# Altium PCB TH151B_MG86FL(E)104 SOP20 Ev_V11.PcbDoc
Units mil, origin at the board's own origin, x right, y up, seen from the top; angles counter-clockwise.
Board outline 2850 x 2110 mil, 2 copper layers (Top Layer, Bottom Layer); 47 components, 39 nets, 238 pads, 101 vias.
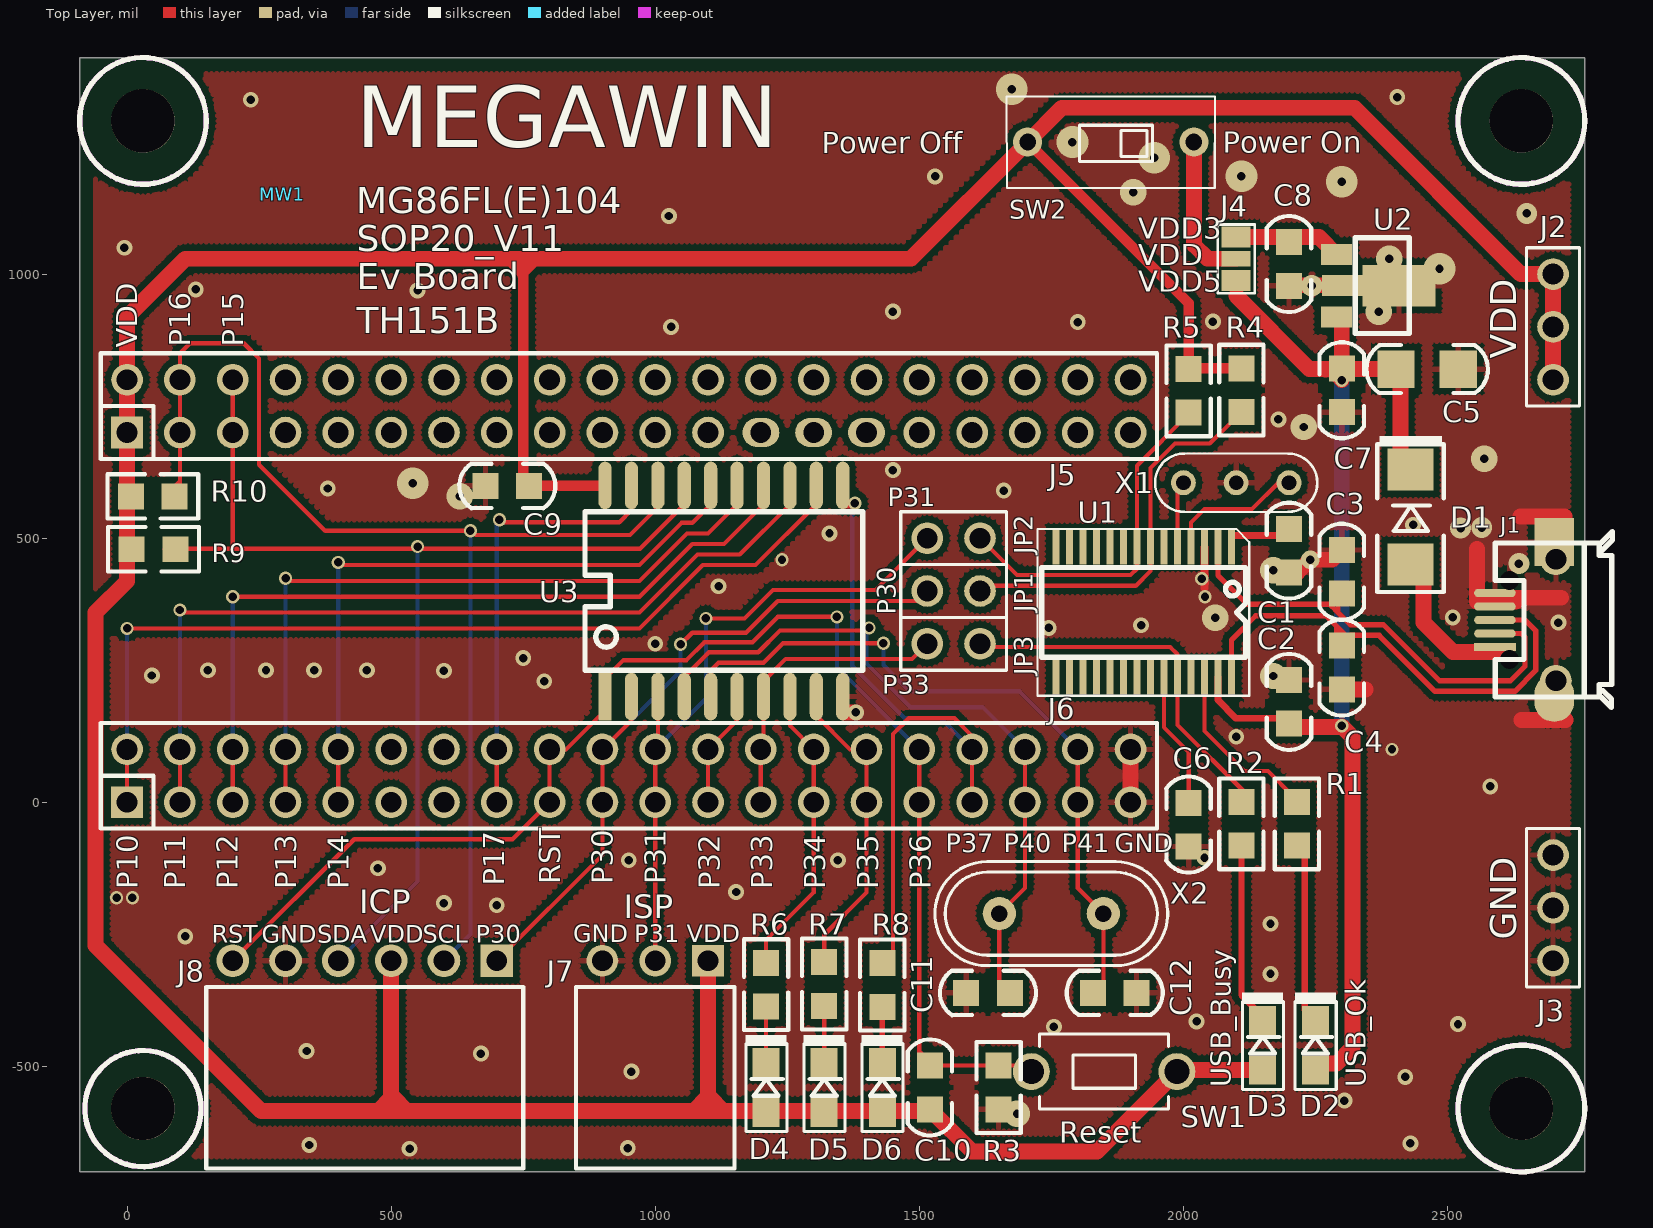
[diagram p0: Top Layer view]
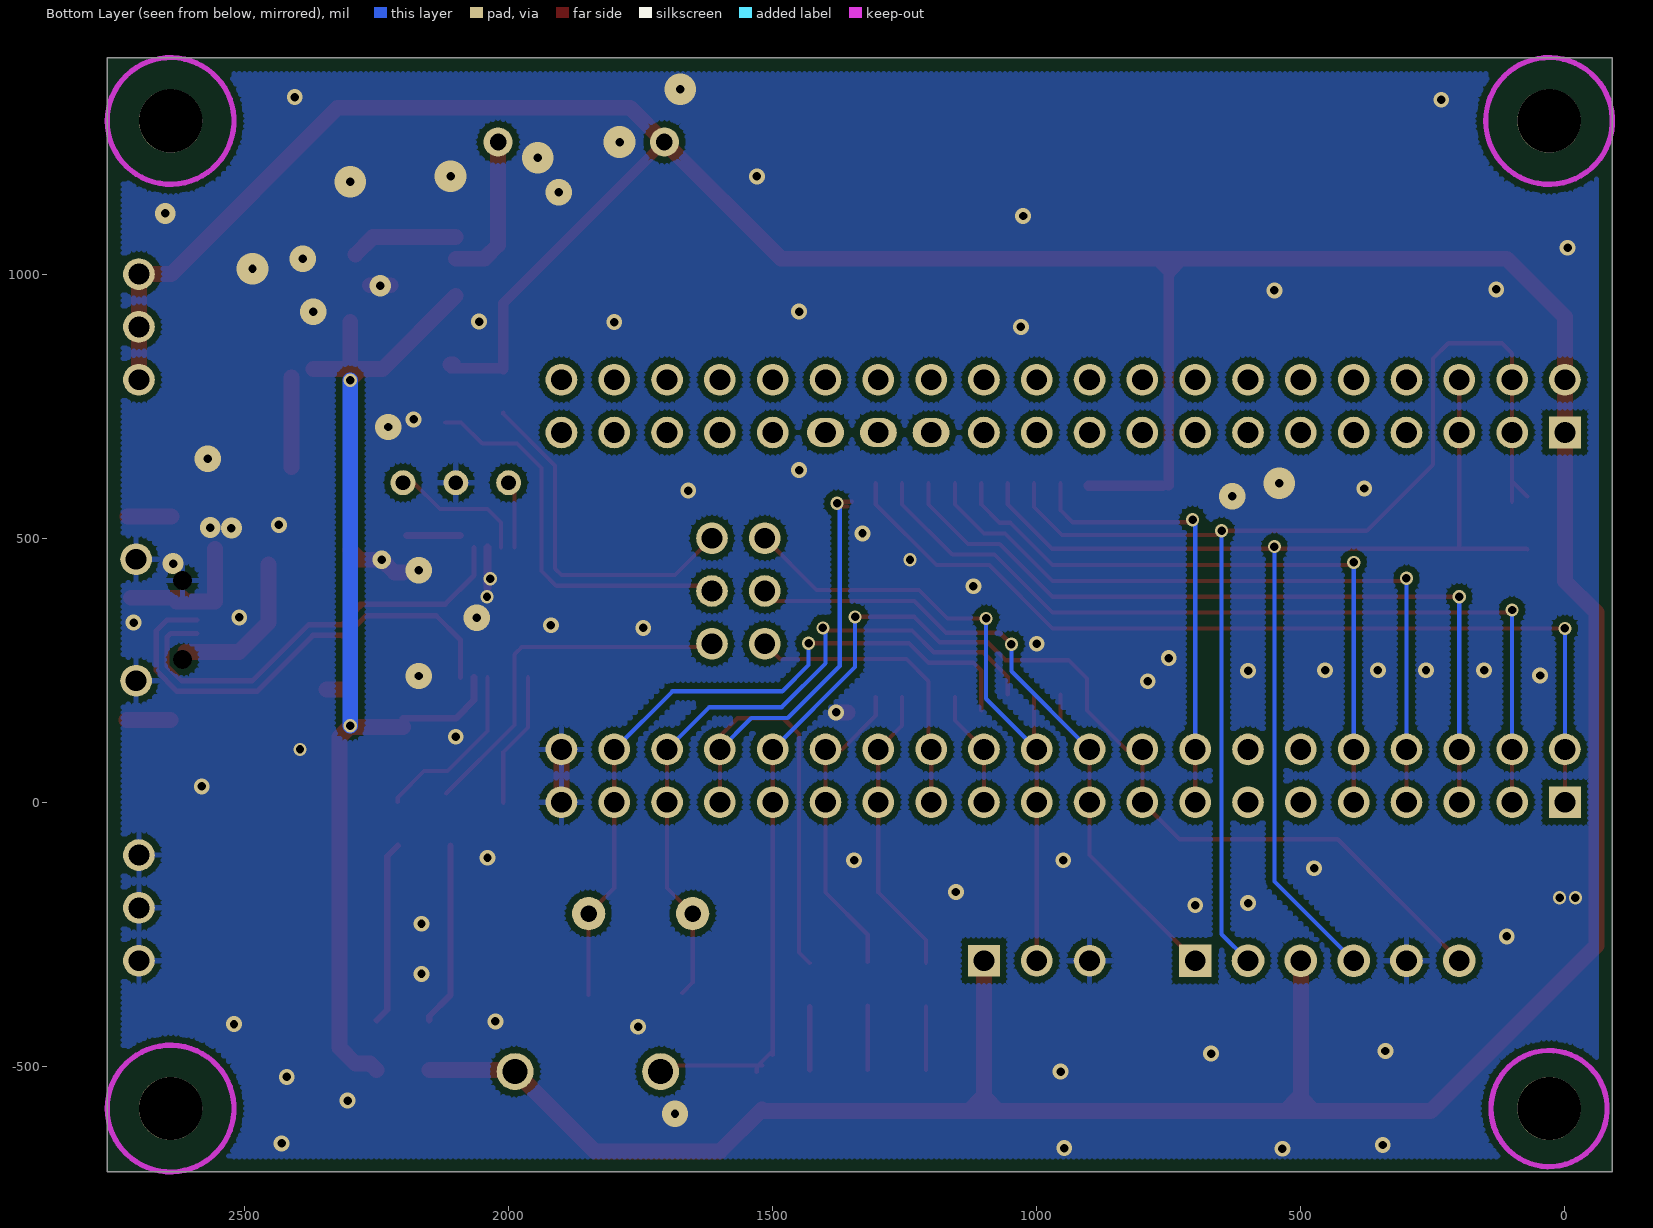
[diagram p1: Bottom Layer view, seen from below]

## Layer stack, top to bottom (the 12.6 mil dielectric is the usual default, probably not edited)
Top Layer: signal copper 1.4
Dielectric: dielectric 12.6, FR-4, Dk 4.8
Bottom Layer: signal copper 1.4

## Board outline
-90,-700 2760,-700 2760,1410 -90,1410

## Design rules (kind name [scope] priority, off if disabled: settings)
Clearance 12 [All] p1 off: gap=12
Clearance 10 [All] p2 off: gap=10
Clearance 6 [All] p3: gap=6
ComponentClearance [All] p1 off: gap=10 collisioncheckmode=3 verticalgap=10 showdistances=FALSE
HoleSize [All] p1: absolutevalues=TRUE maxlimit=500 minlimit=1 maxpercent=80.000 minpercent=20.000
MinimumSolderMaskSliver [All] p1 off: minsoldermaskwidth=10
PolygonConnect VIA [ISVIA] p1: connectstyle=Direct reliefconductorwidth=10 reliefentries=4 polygonreliefangle="90 Angle"
PolygonConnect [All] p2: connectstyle=Relief reliefconductorwidth=10 reliefentries=4 polygonreliefangle="90 Angle"
RoomDefinition "TH151B_MG86FL(E)104 SOP20 Ev_V10" [InComponentClass('TH151B_MG86FL(E)104 SOP20 Ev_V10')] p1: confinementstyle=ConfineIn formatcopy=TRUE lockcomponents=FALSE outline -510,-1045 2905,-1045 2905,1630 -510,1630
RoutingVias [All] p1: holewidth=16 width=25 viastyle="Through Hole" minholewidth=16 minwidth=24 maxholewidth=28 maxwidth=50
SilkToSilkClearance [All] p1 off: silktosilkclearance=10
SilkscreenOverComponentPads [All] p1 off: minsilkscreentomaskgap=10
SolderMaskExpansion [All] p1 off: expansion=4
Width [All] p1: maxlimit=200 minlimit=6 preferedwidth=10
23 further rules are at their usual default settings.

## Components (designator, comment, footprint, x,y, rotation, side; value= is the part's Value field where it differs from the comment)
C1 "4.7uF" 0805C 2200,476.34 r270 top
C2 "0.1uF" 0805C 2200,190 r270 top
C3 "15pF" 0805C 2300,436.34 r90 top
C4 "15pF" 0805C 2300,255 r270 top
C5 "4.7uF" 1206C 2461.62,820 r0 top
C6 "0.1uF" 0805C 2010,-42.34 r90 top
C7 "0.1uF" 0805C 2300,780 r270 top
C8 "4.7uF" 0805C 2200,1019 r270 top
C9 "0.1uF" 0805C 720,599 r180 top
C10 "1u" 0805C 1520,-540 r90 top
C11 "NC" 0805C 1630,-361 r180 top
C12 "NC" 0805C 1870,-361 r0 top
D1 "1N5817" D5817_SMD_1 2430,540 r270 top
D2 "Yellow" 0805D 2250,-460 r90 top
D3 "RED" 0805D 2150,-460 r90 top
D4 "Green" 0805D 1210,-540 r90 top
D5 "RED" 0805D 1320,-540 r90 top
D6 "Green" 0805D 1430,-540 r90 top
J1 "Micro USB母座" JACK_USB_SMD290X220P065 2590,345 r180 top
J2 "*" PS3P254 2700,800 r90 top
J3 "*" PS3P254 2700,-100 r270 top
J4 "*" JUMP3_SMD 2100,1029 r90 top
J5 "*" PS20X2P254 0,700 r0 top locked
J6 "*" PS20X2p254 0,0 r0 top
J7 "*" PS3P254f_90 1100,-300 r180 top
J8 "*" PS6P254F_90 700,-300 r180 top
JP1 "JUMPER2" PS2P254 1515,400 r0 top
JP2 "JUMPER2" PS2P254 1515,500 r0 top
JP3 "JUMPER2" PS2P254 1515,300 r0 top
MW1 "MW-A4" MEGAWIN_T 294.19,1151.19 r0 top
R1 "1K" 0805R 2215,-41 r270 top
R2 "1K" 0805R 2110,-41 r270 top
R3 "47K" 0805R 1650,-540 r90 top
R4 "4.7K" 0805R 2110,780.34 r270 top
R5 "4.7K" 0805R 2010,779 r270 top
R6 "1K" 0805R 1210,-345.42 r270 top
R7 "1K" 0805R 1320,-344.08 r270 top
R8 "1K" 0805R 1430,-346 r270 top
R9 "4.7K" 0805R 50,479 r180 top
R10 "4.7K" 0805R 48.66,579 r180 top
SW1 "SW TACT-SPST" SW_T_2P 1850,-510 r0 top
SW2 "-" DIP2_SW 2020,1250 r180 top
U1 "MA101_TSSOP28" TSSOP28_170P065 1924.84,359.52 r180 top
U2 "AIC1734-33(SOT-89)" SOT89 2290,978.06 r270 top
U3 "MG86Fx104(20-SOP)" SO20_300P127 1130,400 r0 top
X1 "6MHz" X3P 2200,605 r180 top
X2 "NC" X49U 1750,-211 r0 top

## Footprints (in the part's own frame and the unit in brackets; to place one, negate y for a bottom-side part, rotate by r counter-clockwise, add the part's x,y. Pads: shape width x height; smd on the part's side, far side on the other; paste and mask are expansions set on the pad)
0805C [mm]
  rect 1.25x1.25 smd: 1(-1.05,0) 2(1.05,0)
  silkscreen extent -2.31,-1.07 2.31,1.07
0805D [mm]
  rect 1.4x1.3 smd: 1(-1.192,0) 2(1.192,0)
  silkscreen extent -2.12,-1 2.53,0.98
0805R [mm]
  rect 1.25x1.25 smd: 1(-1.05,0) 2(1.05,0)
  silkscreen extent -2.18,-1.07 2.18,1.07
1206C [mm]
  rect 1.8x1.8 smd: 1(-1.5,0) 2(1.5,0)
  silkscreen extent -2.92,-1.15 2.92,1.16
D5817_SMD_1 [mil]
  rect 80x86.61 smd: 1(90,0) 2(-90,0)
  silkscreen extent -153,-63 142,63
DIP2_SW [mm]
  round 1.4 hole 0.8: 1(0,0) 2(8,0)
  silkscreen extent -1.02,-2.2 9.02,2.2
JACK_USB_SMD290X220P065 [mm]
  rect 1.9x1.8 on Mech2: 0(-2.85,-1.15) 0(-2.85,1.15)
  round 0.8 hole 0.9 unplated: 1(-0.7,1.9) 5(-0.7,-1.9)
  rect 2x0.4 smd: 1(0,1.3)
  oval 2x0.4 smd: 2(0,0.65) 3(0,0) 4(0,-0.65) 5(0,-1.3)
  round 1.524 hole 1: 5(-2.931,2.921) 5(-2.931,-2.921)
  oval 1.9x2.3 smd: 5(-2.85,3.75)
  rect 1.9x2.3 smd: 5(-2.85,-3.75)
  silkscreen extent -5.65,-4.25 -0.01,4.2
JUMP3_SMD [mil]
  rect 40x55 smd: 1(-41,0) 3(41,0)
  rect 30x55 smd: 2(0,0)
  silkscreen extent -65,-35 65,35
MEGAWIN_T [mil]
PS2P254 [mil]
  round 60 hole 39.37: 1(0,0) 2(100,0)
  silkscreen extent -50,-50 150,50
PS3P254 [mil]
  round 60 hole 39.37: 1(0,0) 2(100,0) 3(200,0)
  silkscreen extent -50,-50 250,50
PS3P254f_90 [mil]
  rect 60x60 hole 39.37: 1(0,0)
  round 60 hole 39.37: 2(100,0) 3(200,0)
  silkscreen extent -50,50 250,394
PS6P254F_90 [mil]
  rect 62x62 hole 39.37: 1(0,0)
  round 62 hole 39.37: 2(100,0) 3(200,0) 4(300,0) 5(400,0) 6(500,0)
  silkscreen extent -50,50 550,394
PS20X2P254 [mil]
  rect 60x60 hole 39.37: 1(0,0)
  round 60 hole 39.37: 2(0,100) 3(100,0) 4(100,100) 5(200,0) 6(200,100) 7(300,0) 8(300,100) 9(400,0) 10(400,100) 11(500,0) 12(500,100) 13(600,0) 14(600,100) 15(700,0) 16(700,100) 17(800,0) 18(800,100) 19(900,0) 20(900,100) 21(1000,0) 22(1000,100) 23(1100,0) 24(1100,100) 26(1200,100) 28(1300,100) 30(1400,100) 31(1500,0) 32(1500,100) 33(1600,0) 34(1600,100) 35(1700,0) 36(1700,100) 37(1800,0) 38(1800,100) 39(1900,0) 40(1900,100)
  oval 70x55 hole 39.37: 25(1200,0) 27(1300,0) 29(1400,0)
  silkscreen extent -50,-50 1950,150
PS20X2p254 [mil]
  rect 60x60 hole 39.37: 1(0,0)
  round 60 hole 39.37: 2(0,100) 3(100,0) 4(100,100) 5(200,0) 6(200,100) 7(300,0) 8(300,100) 9(400,0) 10(400,100) 11(500,0) 12(500,100) 13(600,0) 14(600,100) 15(700,0) 16(700,100) 17(800,0) 18(800,100) 19(900,0) 20(900,100) 21(1000,0) 22(1000,100) 23(1100,0) 24(1100,100) 25(1200,0) 26(1200,100) 27(1300,0) 28(1300,100) 29(1400,0) 30(1400,100) 31(1500,0) 32(1500,100) 33(1600,0) 34(1600,100) 35(1700,0) 36(1700,100) 37(1800,0) 38(1800,100) 39(1900,0) 40(1900,100)
  silkscreen extent -50,-50 1950,150
SO20_300P127 [mil]
  rect 25x90 smd: 1(-225,-200)
  oval 25x90 smd: 2(-175,-200) 3(-125,-200) 4(-75,-200) 5(-25,-200) 6(25,-200) 7(75,-200) 8(125,-200) 9(175,-200) 10(225,-200) 11(225,200) 12(175,200) 13(125,200) 14(75,200) 15(25,200) 16(-25,200) 17(-75,200) 18(-125,200) 19(-175,200) 20(-225,200)
  silkscreen extent -263,-150 263,150
SOT89 [mm]
  rect 1.016x1.5 smd: 1(-1.5,0) 3(1.5,0)
  rect 2x3.5 smd: 2(0,3)
  rect 1.016x2.6 smd: 2(0,0.6)
  silkscreen extent -2.3,0.9 2.3,3.5
SW_T_2P [mil]
  round 70 hole 47.24: 1(-137.79,0) 2(137.79,0)
  silkscreen extent -122,-71 122,71
TSSOP28_170P065 [mil]
  rect 13x65 smd: 1(-166.34,-123) 2(-140.75,-123) 3(-115.16,-123) 4(-89.57,-123) 5(-63.98,-123) 6(-38.39,-123) 7(-12.79,-123) 8(12.8,-123) 9(38.39,-123) 10(63.98,-123) 11(89.57,-123) 12(115.16,-123) 13(140.75,-123) 14(166.34,-123) 15(166.34,123) 16(140.75,123) 17(115.16,123) 18(89.57,123) 19(63.98,123) 20(38.39,123) 21(12.8,123) 22(-12.79,123) 23(-38.39,123) 24(-63.98,123) 25(-89.57,123) 26(-115.16,123) 27(-140.75,123) 28(-166.34,123)
  silkscreen extent -200,-158 201,158
X3P [mm]
  round 1.2 hole 0.711: 1(0,0) 2(5.08,0) 3(2.54,0)
  silkscreen extent -1.36,-1.4 6.44,1.4
X49U [mm]
  round 1.6 hole 0.8: 1(-2.5,0) 2(2.5,0)
  silkscreen extent -5.6,-2.5 5.6,2.5

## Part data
C1 C5 C8: library part CAP
C2 C3 C4 C6 C7 C9: library part "CAP NP"
C10: library part C
C11 C12: library part "C NP"
D1: library part DIODE_ZD, "Schottky Diode"
D2 D3 D4 D5 D6: library part LED
J1: library part CON5, "Connector"
J2 J3 J4 J7: library part CON3
J5 J6: library part CON40A
J8: library part CON6
R1 R2 R4 R5 R6 R7 R8: library part R_Dup1
R3 R9 R10: library part R
SW2: library part SW-2
U2: library part AIC1734-33(SOT-89)_0
U3: library part MG86Fx104(20-DIP)
X1: library part CRYSTAL_RC
X2: library part CRYSTAL

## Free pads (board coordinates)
  round 120 hole 120 unplated: 0(30,-580) 0(30,1290) 0(2640,-580) 0(2640,1290)

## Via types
v1: diameter 30, hole 16, Top Layer to Bottom Layer, tented both sides, 56 vias
v2: diameter 25, hole 16, Top Layer to Bottom Layer, tented both sides, 22 vias
v3: diameter 50, hole 16, Top Layer to Bottom Layer, tented both sides, 10 vias
v4: diameter 60, hole 16, Top Layer to Bottom Layer, tented both sides, 7 vias
v5: diameter 39.37, hole 16, Top Layer to Bottom Layer, tented both sides, 3 vias
v6: diameter 40, hole 16, Top Layer to Bottom Layer, tented both sides, 2 vias
v7: diameter 35, hole 16, Top Layer to Bottom Layer, tented both sides, 1 vias

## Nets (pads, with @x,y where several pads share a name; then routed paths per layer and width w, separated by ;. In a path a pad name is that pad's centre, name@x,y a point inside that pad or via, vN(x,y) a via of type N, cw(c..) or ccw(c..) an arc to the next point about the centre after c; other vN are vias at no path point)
D+: C4.1 J1.3 U1.28 | length 924.9
  Top Layer w10: U1.28 2091.18,307.18 2137,353 2270,353 2290.64,332.36 ; C4.1@2290.64,315.03 2290.64,332.36 ; C4.1@2300,305.67 2307,312.67 2307,316 2290.64,332.36 ; C4.1@2315,315 2316,316 2370.72,316 2476.72,210 2627.72,210 2667,249.28 2667,324.93 2646.93,345 J1.3
D-: C3.1 J1.2 U1.2 | length 863.2
  Top Layer w10: U1.2 2065.59,429.41 2120,375 2281,375 2281,371 2293,359 ; C3.1@2293,376.33 2293,359 ; J1.2 2640.43,319.41 2647,312.84 2647,257.56 2619.44,230 2485,230 2379,336 2316,336 2293,359
GND_POWER: C1.2 C2.1 C3.2 C4.2 C5.2 C6.1 C7.2 C8.2 C9.2 C11.2 C12.2 J1.4 J1.5 J3.1 J3.2 J3.3 J6.39 J6.40 J7.3 J8.5 R3.1 U1.3 U2.2 U3.10 X1.3 | length 836.6
  Top Layer w15: 2040,406 v2@2040,416 ; U1.3 v2@2040,416 ; v2@2041,415 v2@2040,416
  Top Layer w30: U3.10@1358,170 v1(1380,170) ; J6.39 J6.40 ; C1.2 2216,435 v7(2240,459) 2281.32,459 C3.2 ; C8.2@2223.34,979 U2.2@2263,979 ; C4.2 2344.66,213.66 ; 2555.87,380.05 2629.29,380.05 ; 2555.87,382.64 2555.87,479.72 ; 2618.54,387.05 2715.63,387.05 ; 2638.28,540.87 2721.82,540.87 ; 2640.28,155.87 2723.82,155.87
  other v1: 535,-656 948,-655 345,-649 2430,-646 2305,-565 2420,-520 955,-510 670,-476 340,-471 1755,-425 2520,-420 2025,-415 2165,-325 110,-254 2165,-230 700,-195 600,-191 1153,-170 475,-125 950,-110 1346,-110 2040,-105 2581,30 2100,124 790,229 47,240 600,249 153,250 263,250 354,250 454,250 750,273 1000,300 1745,330 1920,335 2710,340 2510,350 1120,409 1330,509 2435,525 1660,590 380,594 1450,629 2180,725 1030,900 1800,909 2056,910 1450,929 550,969 130,971 -5,1050 1026,1110 1530,1185 234,1330 2405,1335
  other v2: -20,-181 10,-181 2395,100 2041,389 2035,423 1240,459
  other v3: 1685,-590 2170,239 2060,349 2170,439 630,579 2570,650 2228,710.5 2370,929 2390,1029 1905,1155
  other v4: 541,604 2485,1010 2300,1175 2110,1185 1945,1220 1790,1250 1675,1350
  other v5: 2525,519 2565,520 2650,1115
  other v6: 2635.29,451.72 2243,978
MA101_RX: JP2.2 R5.2 U1.8 | length 677.8
  Top Layer w8: JP2.2@1600,500 JP2.2@1607.5,492.5 ; JP2.2 1685,430 1900,430 1912.05,442.05 U1.8 1912.05,637.05 2010,735 R5.2
MA101_TX: JP1.2 R4.2 U1.7 | length 760.5
  Top Layer w8: JP1.2@1610,390 1630,410 1910,410 1937.64,437.64 1937.64,632.64 1984,679 2050,679 2090,719 R4.2@2120,719
NetC1_1: C1.1 U1.1 | length 102.5
  Top Layer w13: U1.1@2091.18,505 C1.1@2193.66,505
NetC6_2: C6.2 U1.23 | length 269.1
  Top Layer w8: 1963.23,191.18 1963.23,179 ; U1.23 1963.23,179 ; C6.2 2010,95 1963.23,141.77 1963.23,179
NetD1_1: D1.1 J1.1 | length 290.1
  Top Layer w30: D1.1@2455,450 2455,340 2510.28,284.72 J1.1@2612.2,284.72
NetD2_2: D2.2 R1.2 | length 347.3
  Top Layer w12: R1.2@2210,-82.34 2230,-102.34 2230,-393.08 D2.2
NetD3_2: D3.2 R2.2 | length 347.3
  Top Layer w12: R2.2 2110,-365 2150,-405 D3.2
NetD4_2: D4.2 R6.2 | length 120.4
  Top Layer w8: D4.2@1210,-507.16 D4.2 R6.2
NetD5_2: D5.2 R7.2 | length 121.7
  Top Layer w8: D5.2@1320,-507.16 D5.2 R7.2
NetD6_2: D6.2 R8.2 | length 119.8
  Top Layer w10: D6.2@1430,-507.16 D6.2 R8.2
NetJ4_2: J4.2 SW2.1 | length 285.8
  Top Layer w30: SW2.1 2020,1055 2046,1029 J4.2
NetU1_4: U1.4 X1.1 | length 263.8
  Top Layer w8: U1.4 2014.41,529.41 2040,555 2130,555 2180,605 X1.1
NetU1_5: U1.5 X1.2 | length 127.1
  Top Layer w8: U1.5 1988.82,593.82 X1.2
P10: J6.1 J6.2 U3.12 | length 1771.3
  Top Layer w8: J6.1 J6.2 ; v2(0,329) 970,329 1090,449 1190,449 1305,564 U3.12 U3.12@1305,604
  Bottom Layer w8: J6.2 v2(0,329)
P11: J6.3 J6.4 U3.13 | length 1643.9
  Top Layer w8: J6.3 J6.4 ; v2@100,359 970,359 1080,469 1160,469 1255,564 U3.13 U3.13@1255,604
  Bottom Layer w8: J6.4 v2(100,364)
P12: J6.5 J6.6 U3.14 | length 1506.5
  Top Layer w8: J6.5 J6.6 ; v2(200,389) 970,389 1070,489 1130,489 1205,564 U3.14 U3.14@1205,604
  Bottom Layer w8: J6.6 v2(200,389)
P13: J6.7 J6.8 U3.15 | length 1379.1
  Top Layer w8: J6.7 J6.8 ; v2@300,419 970,419 1060,509 1100,509 1155,564 U3.15 U3.15@1155,604
  Bottom Layer w8: J6.8 v2(300,424)
P14: J6.9 J6.10 U3.16 | length 1246.6
  Top Layer w8: J6.9 J6.10 ; v2@400,449 970,449 1050,529 1070,529 1105,564 U3.16 U3.16@1105,604
  Bottom Layer w8: J6.10 v2(400,454)
P15: J5.5 J5.6 J8.4 R9.1 U3.17 | length 2224
  Top Layer w8: R9.1@71.34,479 72.34,480 200,480 ; J5.6 J5.5 200,480 ; U3.17@1055,604 U3.17 1055,564 971,480 200,480
  Bottom Layer w8: J8.4 550,-150 v2@550,483
  other v2: 550,484
P16: J5.3 J5.4 J8.2 R10.1 U3.18 | length 2628.2
  Top Layer w8: R10.1@71.34,579 100,607.66 ; R10.1@100,569 100,607.66 ; 600,514 375,514 ; U3.18@1005,604 U3.18 1005,559 952,506 660,506 652,514 v2(650,514) 375,514 ; 100,607.66 J5.3 J5.4 100,850 119,869 221,869 250,840 250,639 375,514
  Bottom Layer w8: J8.2 650,-250 v2@650,513
P17: J6.15 J6.16 U3.19 | length 855.3
  Top Layer w8: J6.15 J6.16 ; v2@705,539 714,530 932,530 955,553 U3.19 U3.19@955,604
  Bottom Layer w8: J6.16 700,534 v2@705,539
  other v2: 705,535
P30_RXD: J6.19 J6.20 J8.1 JP1.1 U3.2 | length 1378.8
  Top Layer w8: J8.1 900,-100 J6.19 J6.20 955,155 U3.2 U3.2@955,204 ; v2(1048,299) 1070,321 1172,321 1232,381 1496,381 JP1.1
  Bottom Layer w8: J6.20 1048,248 v2(1048,299)
P31_TXD: J6.21 J6.22 J7.2 JP2.1 U3.3 | length 1275.8
  Top Layer w8: J7.2 J6.21 J6.22 1005,105 U3.3 U3.3@1005,204 ; v2(1096,348) 1169,348 1223,402 1417,402 JP2.1
  Bottom Layer w8: J6.22 1096,196 v2(1096,348)
P32: J6.23 J6.24 U3.6 | length 221.8
  Top Layer w8: J6.23 J6.24 1155,155 U3.6@1155,199
P33: J6.25 J6.26 JP3.1 U3.7 | length 570.5
  Top Layer w8: J6.25 J6.26 1205,105 U3.7 1205,229 1247,271 1486,271 JP3.1
P34: J6.27 J6.28 R6.1 U3.8 | length 559
  Top Layer w8: R6.1 1210,-261 1300,-171 J6.27 J6.28 1255,145 U3.8@1255,199
P35: J6.29 J6.30 R7.1 U3.9 | length 592.4
  Top Layer w8: U3.9@1305,199 1305,164 1369,100 J6.30 J6.29 1400,-171 1320,-251 R7.1
P36: C10.2 J6.17 J6.18 J6.31 J6.32 J8.6 R3.2 SW1.1 U3.1 | length 2637.3
  Top Layer w8: J8.6 430,-70 730,-70 J6.17 J6.18 831,100 905,174 U3.1 905,234 940,269 1059,269 1093,303 1184,303 1232,351 v2(1344,351) ; C10.2@1500,-478.66 J6.31 J6.32 ; C10.2@1503.83,-474.83 C10.2@1523.83,-494.83 ; C10.2 R3.2 1699.7,-498.66 SW1.1@1712.21,-511.16 ; C10.2@1530,-511 C10.2@1530,-501
  Bottom Layer w8: v2(1344,351) 1344,256 J6.32
P37: J6.33 J6.34 R8.1 U3.11 | length 1377.3
  Top Layer w8: U3.11@1350,569 v2@1378,569 ; U3.11@1359,560 v2@1374,560 ; R8.1 1450,-284.66 1450,129 1480,159 1566.65,159 1600,125.65 J6.34 J6.33
  Bottom Layer w8: v2@1373,556 1373,258 1471.5,159.5 1540.5,159.5 J6.34
  other v2: 1378,566
P40: C11.1 J6.35 J6.36 U3.4 X2.1 | length 1343.2
  Top Layer w8: U3.4@1055,204 1055,237 1102,284 1195,284 1236,325 v2@1405,325 ; C11.1 1651.57,-341.24 X2.1 1700,-162.58 J6.35 J6.36
  Bottom Layer w8: v2@1400,330 1400,263 1483,180 1620,180 J6.36
  other v2: 1405,330
P41: C12.1 J6.37 J6.38 U3.5 X2.2 | length 1387
  Top Layer w8: U3.5@1105,174 U3.5 U3.5@1105,201 ; U3.5@1105,204 U3.5@1105,201 ; v2(1432,301) 1242,301 1205,264 1120,264 1105,249 U3.5@1105,201 ; J6.38 J6.37 1800,-162.58 X2.2 1848.66,-211.24 C12.1@1848.66,-365
  Bottom Layer w8: v2(1432,301) 1432,260 1482,210 1690,210 J6.38
USB_BUSY: JP3.2 R2.1 U1.24 | length 1099.2
  Top Layer w8: JP3.2@1606,294 1975,294 ; 1710,294 1975,294 ; 2080,55 1988.82,146.18 ; R2.1@2118,17 1988.82,146.18 ; 1975,294 1988.82,280.18 U1.24 1988.82,146.18
USB_OK: R1.1 U1.26 | length 344.6
  Top Layer w8: 2040,191.18 2040,179 ; U1.26 2040,179 ; R1.1@2210,0.34 2210,9 2160,59 2116,59 2040,135 2040,179
VDD: C9.1 C10.1 D3.1 D4.1 D5.1 D6.1 J2.1 J2.2 J2.3 J5.1 J5.2 J7.1 J8.3 R4.1 R5.1 R9.2 R10.2 SW1.2 SW2.2 U3.20 | length 9204.2
  Top Layer w15: 464,-584.9 500,-548.9 501,-547.9 ; 504,-547.9 541,-584.9 ; 712,1034 717,1029 748.5,997.5 ; 748,997 748.5,997.5 ; 749,997 748.5,997.5 ; 785,1034 780,1029 750,999 749,998 748.5,997.5 ; 1062,-584.9 1099,-547.9 ; 1103,-547.9 1140,-584.9
  Top Layer w20: 749,997 749,998 749,1029 ; C9.1@750,600 750,999 750,1029 ; C9.1 U3.20@902,599 ; SW2.2 2010,945.04 R5.1 ; R5.1@2011.34,821.68 R4.1
  Top Layer w30: R9.2@0,465 R9.2@0,479 ; J8.3 500,-548.9 500,-584.9 ; J7.1 1100,-584.9 ; C10.1 C10.1@1523.56,-584.9 ; SW1.2 1836.79,-661 1599.66,-661 C10.1@1523.56,-584.9 ; SW1.2@1987.79,-506.92 D3.1 ; R4.1@2104.95,829 R4.1@2110,829 ; 2500,1139 2639,1000 ; J2.1 J2.2 J2.3 2639,1000 ; R9.2@0,479 J5.1 J5.2 0,919 110,1029 717,1029 749,1029 750,1029 780,1029 1484.04,1029 SW2.2 1770.04,1315 2324,1315 2639,1000 ; R9.2@0,479 0,419 -60,359 -60,-271 253.9,-584.9 464,-584.9 500,-584.9 ; 500,-584.9 541,-584.9 1062,-584.9 1100,-584.9 ; 1100,-584.9 1140,-584.9 C10.1@1523.56,-584.9
VDD3: C8.1 J4.3 U2.1 | length 203.6
  Top Layer w30: J4.3 2257.11,1070 U2.1
VDD5: C2.2 C5.1 C7.1 D1.2 D2.1 J4.1 U1.27 U2.3 | length 2264.1
  Top Layer w13: U1.27 2065.59,193.41 2100,159 C2.2@2200,159
  Top Layer w30: 2100,959 2238.66,820.34 2268.66,820.34 ; C2.2@2200,142.32 v2@2297.32,142.32 ; D2.1 2261.92,-495 2290,-495 2320,-465 2320,124 v2@2300,144 ; 2269.33,819.67 2268.66,820.34 ; v2(2300,799) 2300,800.34 C7.1@2280,820.34 ; U2.3@2300,909 C7.1 C7.1@2300,820.34 ; C5.1@2370,820.34 C7.1@2300,820.34 ; D1.2@2410.87,635 C5.1@2410.87,804.72 ; 2268.66,820.34 C7.1@2280,820.34 ; C7.1@2280,820.34 C7.1@2300,820.34
  Bottom Layer w30: v2(2300,145) v2(2300,799)
pads on no net: J1.0 J5.7 J5.8 J5.9 J5.10 J5.11 J5.12 J5.13 J5.14 J5.15 J5.16 J5.17 J5.18 J5.19 J5.20 J5.21 J5.22 J5.23 J5.24 J5.25 J5.26 J5.27 J5.28 J5.29 J5.30 J5.31 J5.32 J5.33 J5.34 J5.35 J5.36 J5.37 J5.38 J5.39 J5.40 J6.11 J6.12 J6.13 J6.14 U1.6 U1.9 U1.10 U1.11 U1.12 U1.13 U1.14 U1.15 U1.16 U1.17 U1.18 U1.19 U1.20 U1.21 U1.22 U1.25

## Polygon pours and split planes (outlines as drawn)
GND_POWER on Top Layer "Bottom Layer-No Net" (hatched 90Degree grid 10 track 10, remove dead copper, pour order 1000): -60,-671 2730,-671 2730,1380 -60,1380
GND_POWER on Bottom Layer "Bottom Layer-No Net" (hatched 90Degree grid 10 track 10, remove dead copper, pour order 1000): -60,-671 2730,-671 2730,1380 -60,1380

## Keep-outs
Keep-Out Layer:
  circle w10: c2640,1290 r120
  circle w10: c30,-580 r110
  circle w10: c30,1290 r120
  circle w10: c2640,-580 r120

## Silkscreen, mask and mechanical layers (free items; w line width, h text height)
Top Overlay:
  circle w10: c2640,1290 r120
  circle w10: c30,-580 r110
  circle w10: c30,1290 r120
  circle w10: c2640,-580 r120
  text "Power On" at 2075,1230 h40
  text "Power Off" at 1315,1229 h40
  text "MG86FL(E)104" at 434.19,1115.19 h50
  text "VDD3" at 1914.25,1067 h40
  text "SOP20_V11" at 435,1043 h50
  text "VDD" at 1914.25,1017 h40
  text "Ev Board" at 435,971 h50
  text "VDD5" at 1914.25,967 h40
  text "TH151B" at 435,888 h50
  text "P16" at 120,862 h40 r90
  text "P15" at 220,862 h40 r90
  text "VDD" at 19,861 h40 r90
  text "VDD" at 2630,840 h50 r90
  text "P31" at 1440,560 h35
  text "P30" at 1455,355 h35 r90
  text "P33" at 1430,205 h35
  text "P37" at 1550,-95 h35
  text "P40" at 1660,-95 h35
  text "P41" at 1770,-95 h35.43
  text "GND" at 1870,-95 h35.43
  text "RST" at 820,-155 h40 r90
  text "P30" at 920,-155 h40 r90
  text "P31" at 1020,-155 h40 r90
  text "P17" at 713.95,-158.05 h40 r90
  text "P10" at 20,-165 h40 r90
  text "P11" at 110,-165 h40 r90
  text "P12" at 210,-165 h40 r90
  text "P13" at 320,-165 h40 r90
  text "P14" at 420,-165 h40 r90
  text "P32" at 1122,-165 h40 r90
  text "P33" at 1222,-165 h40 r90
  text "P34" at 1322,-165 h40 r90
  text "P35" at 1422,-165 h40 r90
  text "P36" at 1522,-165 h40 r90
  text "ICP" at 440,-210 h45
  text "ISP" at 940,-220 h45
  text "GND" at 2630,-260 h50 r90
  text "GND" at 845,-265 h33
  text "P31" at 960,-265 h33
  text "VDD" at 1060,-265 h33
  text "RST" at 160,-266 h33
  text "GND" at 255,-266 h33
  text "SDA" at 360,-266 h33
  text "VDD" at 460,-266 h33
  text "SCL" at 560,-266 h33
  text "P30" at 660,-266 h33
  text "USB_Busy" at 2090,-540 h38 r90
  text "USB_Ok" at 2345,-540 h38 r90
  text "Reset" at 1765,-645 h40
Mechanical 1:
  the board outline again, w13

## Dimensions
-90,1410 to -90,-700 on Top Overlay
-90,-700 to 2760,-700 on Top Overlay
